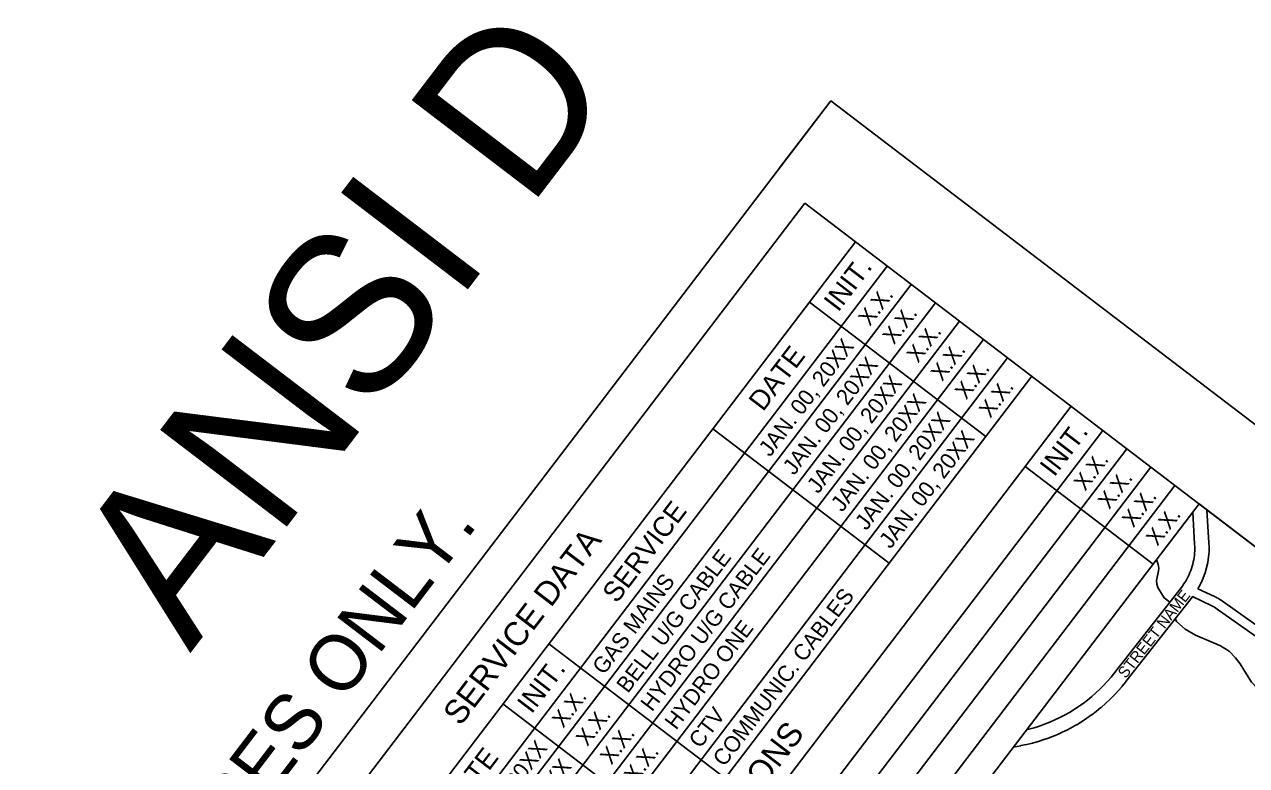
# Model space of a CAD drawing. Extents: x 599744 to 600217, y 4827560 to 4828065.
# Drawn here: x 599948.5 to 600025.2, y 4828018.5 to 4828065 of the extents above; entities that cross this region are included whole.
import ezdxf

# ---------------------------------------------------------------- set-up
doc = ezdxf.new("R2010")
doc.units = 0
for name, color, linetype in [('Default', 7, 'Continuous'), ('G-ANNO-KEYP', 7, 'Continuous'), ('G-ANNO-NPLT', 7, 'Continuous'), ('G-ANNO-TTLB-TEXT', 7, 'Continuous'), ('G-TTLB-OTLN', 7, 'Continuous'), ('G-TTLB-OTLN-PB', 7, 'Continuous')]:
    doc.layers.add(name, color=color, linetype=linetype)

msp = doc.modelspace()

# ---------------------------------------------------------------- linework, layer by layer
at = {"layer": 'G-ANNO-KEYP'}
for points in [[(600011.403, 4828020.775), (600011.528, 4828020.805), (600011.861, 4828020.898), (600012.189, 4828021.002), (600012.514, 4828021.117), (600012.835, 4828021.244), (600013.151, 4828021.381), (600013.462, 4828021.529), (600013.768, 4828021.688), (600014.069, 4828021.857), (600014.363, 4828022.037), (600014.651, 4828022.226), (600014.933, 4828022.425), (600015.207, 4828022.634), (600015.474, 4828022.851), (600015.734, 4828023.079), (600015.985, 4828023.314), (600016.229, 4828023.558), (600016.464, 4828023.811), (600016.69, 4828024.071), (600016.909, 4828024.342), (600021.07, 4828029.664), (600021.156, 4828029.778), (600021.236, 4828029.892), (600021.313, 4828030.009), (600021.385, 4828030.129), (600021.453, 4828030.251), (600021.516, 4828030.375), (600021.576, 4828030.501), (600021.631, 4828030.629), (600021.681, 4828030.76), (600021.727, 4828030.891), (600021.769, 4828031.024), (600021.806, 4828031.159), (600021.838, 4828031.295), (600021.865, 4828031.432), (600021.888, 4828031.57), (600021.906, 4828031.708), (600021.92, 4828031.847), (600021.928, 4828031.986), (600021.932, 4828032.126), (600021.93, 4828032.265), (600021.925, 4828032.382), (600021.925, 4828032.382), (600021.925, 4828032.382), (600021.924, 4828032.409), (600021.923, 4828032.435), (600021.804, 4828034.408)], [(600022.696, 4828034.553), (600022.821, 4828032.489), (600022.822, 4828032.459), (600022.822, 4828032.459), (600022.823, 4828032.452), (600022.824, 4828032.421), (600022.824, 4828032.421), (600022.829, 4828032.296), (600022.829, 4828032.295), (600022.83, 4828032.281), (600022.831, 4828032.126), (600022.83, 4828032.123), (600022.831, 4828032.11), (600022.827, 4828031.955), (600022.826, 4828031.952), (600022.826, 4828031.94), (600022.817, 4828031.785), (600022.815, 4828031.781), (600022.816, 4828031.769), (600022.801, 4828031.615), (600022.799, 4828031.611), (600022.799, 4828031.6), (600022.779, 4828031.446), (600022.777, 4828031.441), (600022.777, 4828031.43), (600022.752, 4828031.278), (600022.749, 4828031.272), (600022.749, 4828031.262), (600022.718, 4828031.11), (600022.715, 4828031.104), (600022.715, 4828031.095), (600022.679, 4828030.944), (600022.676, 4828030.937)], [(600020.365, 4828028.762), (600020.024, 4828029.037), (600019.608, 4828029.696), (600019.55, 4828029.892), (600019.527, 4828030.122), (600019.653, 4828030.741), (600019.675, 4828030.912), (600019.643, 4828031.141), (600019.541, 4828031.442)], [(600022.676, 4828030.937), (600022.675, 4828030.929), (600022.634, 4828030.78), (600022.631, 4828030.772), (600022.63, 4828030.765), (600022.584, 4828030.617), (600022.58, 4828030.609), (600022.579, 4828030.602), (600022.528, 4828030.456), (600022.523, 4828030.447), (600022.523, 4828030.441), (600022.466, 4828030.297), (600022.461, 4828030.287), (600022.46, 4828030.282), (600022.399, 4828030.14), (600022.394, 4828030.13), (600022.393, 4828030.126), (600022.327, 4828029.985), (600022.321, 4828029.975), (600022.32, 4828029.971), (600022.249, 4828029.833), (600022.243, 4828029.823), (600022.242, 4828029.82), (600022.167, 4828029.684), (600022.159, 4828029.673), (600022.159, 4828029.671), (600022.125, 4828029.615)], [(600021.796, 4828029.132), (600021.786, 4828029.119), (600021.781, 4828029.113), (600021.781, 4828029.113), (600017.615, 4828023.785), (600017.615, 4828023.785), (600017.61, 4828023.779), (600017.384, 4828023.499), (600017.383, 4828023.499), (600017.374, 4828023.487), (600017.138, 4828023.215), (600017.137, 4828023.215), (600017.127, 4828023.204), (600016.882, 4828022.94), (600016.88, 4828022.939), (600016.871, 4828022.929), (600016.617, 4828022.674), (600016.615, 4828022.673), (600016.606, 4828022.663), (600016.343, 4828022.417), (600016.34, 4828022.416), (600016.332, 4828022.407), (600016.061, 4828022.169), (600016.057, 4828022.168), (600016.049, 4828022.159), (600015.77, 4828021.932), (600015.765, 4828021.93), (600015.758, 4828021.922), (600015.471, 4828021.704), (600015.466, 4828021.702), (600015.458, 4828021.695), (600015.164, 4828021.487), (600015.159, 4828021.485), (600015.152, 4828021.478), (600014.851, 4828021.281), (600014.844, 4828021.278), (600014.838, 4828021.272), (600014.53, 4828021.085), (600014.523, 4828021.083), (600014.517, 4828021.077), (600014.203, 4828020.901), (600014.195, 4828020.898), (600014.189, 4828020.893), (600013.869, 4828020.727), (600013.861, 4828020.725), (600013.856, 4828020.721), (600013.53, 4828020.566), (600013.521, 4828020.563), (600013.516, 4828020.559), (600013.186, 4828020.416), (600013.176, 4828020.413), (600013.172, 4828020.41), (600012.837, 4828020.278), (600012.826, 4828020.275), (600012.822, 4828020.272), (600012.483, 4828020.152), (600012.471, 4828020.149), (600012.468, 4828020.147), (600012.125, 4828020.038), (600012.113, 4828020.035), (600012.11, 4828020.034), (600011.763, 4828019.937), (600011.75, 4828019.934), (600011.748, 4828019.933), (600011.398, 4828019.848), (600011.385, 4828019.845), (600011.383, 4828019.844)], [(600026.724, 4828025.939), (600023.332, 4828028.341), (600023.251, 4828028.396), (600023.169, 4828028.447), (600023.086, 4828028.496), (600023.001, 4828028.541), (600021.796, 4828029.132)], [(600027.068, 4828026.429), (600023.676, 4828028.831), (600023.675, 4828028.831), (600023.671, 4828028.834), (600023.583, 4828028.894), (600023.582, 4828028.894), (600023.574, 4828028.9), (600023.484, 4828028.957), (600023.483, 4828028.957), (600023.475, 4828028.962), (600023.383, 4828029.016), (600023.381, 4828029.016), (600023.373, 4828029.021), (600023.279, 4828029.072), (600023.277, 4828029.072), (600023.27, 4828029.076), (600023.174, 4828029.123), (600023.173, 4828029.124), (600023.169, 4828029.126), (600022.125, 4828029.615)], [(600031.423, 4828022.843), (600031.069, 4828022.999), (600030.258, 4828023.267), (600029.409, 4828023.358), (600028.876, 4828023.215), (600028.192, 4828022.961), (600027.646, 4828022.814), (600027.113, 4828022.802), (600026.619, 4828022.899), (600026.276, 4828023.086), (600025.874, 4828023.361), (600025.496, 4828023.753), (600025.019, 4828024.527), (600024.778, 4828024.893), (600024.478, 4828025.28), (600024.088, 4828025.705), (600023.545, 4828026.035), (600022.805, 4828026.349), (600021.978, 4828026.699), (600021.327, 4828027.074), (600020.789, 4828027.56), (600020.706, 4828027.738)], [(600011.383, 4828019.844), (600011.031, 4828019.771), (600011.023, 4828019.77), (600011.023, 4828019.77), (600010.572, 4828019.685)]]:
    msp.add_lwpolyline(points, dxfattribs=at)
at = {"layer": 'G-TTLB-OTLN'}
for p, q in [((599758.445, 4827740.467), (599997.478, 4828053.792)), ((599997.478, 4828053.792), (600211.005, 4827890.894)), ((600000.656, 4828051.367), (599962.201, 4828000.96)), ((599962.203, 4828000.958), (600000.658, 4828051.366)), ((600002.644, 4828049.851), (599964.188, 4827999.443)), ((600004.155, 4828048.698), (599965.699, 4827998.291)), ((600005.665, 4828047.546), (599967.21, 4827997.138)), ((599997.775, 4828047.591), (600008.826, 4828039.16)), ((600007.176, 4828046.394), (599968.72, 4827995.986)), ((600008.686, 4828045.241), (599970.231, 4827994.834)), ((600010.197, 4828044.089), (599971.741, 4827993.681)), ((600011.708, 4828042.936), (599973.252, 4827992.529)), ((600014.172, 4828041.056), (599975.717, 4827990.648)), ((600016.16, 4828039.54), (599977.704, 4827989.132)), ((599991.71, 4828039.64), (600002.761, 4828031.209)), ((600017.67, 4828038.387), (599979.215, 4827987.98)), ((600019.181, 4828037.235), (599980.725, 4827986.827)), ((600011.292, 4828037.28), (600019.322, 4828031.154)), ((600020.692, 4828036.082), (599982.236, 4827985.675)), ((599981.429, 4828026.164), (599992.48, 4828017.733)), ((599978.548, 4828022.387), (599989.599, 4828013.956))]:
    msp.add_line(p, q, dxfattribs=at)
msp.add_lwpolyline([(599983.747, 4827984.522), (600022.202, 4828034.93), (600058.02, 4828007.605), (600019.565, 4827957.197)], close=True, dxfattribs=at)
at = {"layer": 'G-TTLB-OTLN-PB'}
for p, q in [((599995.896, 4828056.005), (599999.105, 4828060.212)), ((599999.105, 4828060.212), (600003.873, 4828056.575))]:
    msp.add_line(p, q, dxfattribs=at)
msp.add_lwpolyline([(599961.599, 4827559.688), (600216.766, 4827894.161), (599999.104, 4828060.213), (599743.938, 4827725.74)], close=True, dxfattribs=at)

# ---------------------------------------------------------------- texts
at = {"layer": 'Default'}
msp.add_text('THIS DRAWING SAMPLE IS INTENDED TO ILLUSTRATE THE NEW CAD STANDARDS FOR ROAD WORKS AND SHOULD BE USED FOR REFERENCE PURPOSES ONLY.', height=3.5, rotation=52.66028, dxfattribs=at).set_placement((599752.419, 4827739.237))
at = {"layer": 'G-ANNO-KEYP'}
msp.add_text('STREET NAME', height=0.7, rotation=51.97933, dxfattribs=at).set_placement((600017.599, 4828023.943))
at = {"layer": 'G-ANNO-NPLT'}
msp.add_text('ANSI D', height=10, rotation=52.66028, dxfattribs=at).set_placement((599958.926, 4828025.549))
at = {"layer": 'G-ANNO-TTLB-TEXT'}
for s, height, rotation, p in [('INIT.', 1.25, 52.66028, (599999.57, 4828046.917)), ('X.X.', 1, 52.66023, (600001.555, 4828046.034)), ('X.X.', 1, 52.66023, (600003.066, 4828044.881)), ('X.X.', 1, 52.66023, (600004.577, 4828043.729)), ('JAN. 00, 20XX', 1, 52.66023, (599995.298, 4828037.83)), ('DATE', 1.25, 52.66028, (599994.86, 4828040.677)), ('X.X.', 1, 52.66023, (600006.088, 4828042.576)), ('JAN. 00, 20XX', 1, 52.66023, (599996.809, 4828036.677)), ('X.X.', 1, 52.66023, (600007.599, 4828041.423)), ('JAN. 00, 20XX', 1, 52.66023, (599998.32, 4828035.524)), ('X.X.', 1, 52.66023, (600009.109, 4828040.271)), ('JAN. 00, 20XX', 1, 52.66023, (599999.83, 4828034.372)), ('JAN. 00, 20XX', 1, 52.66023, (600001.342, 4828033.219)), ('INIT.', 1.25, 52.66028, (600013.118, 4828036.581)), ('JAN. 00, 20XX', 1, 52.66023, (600002.852, 4828032.067)), ('X.X.', 1, 52.66023, (600015.056, 4828035.7)), ('X.X.', 1, 52.66023, (600016.566, 4828034.547)), ('SERVICE', 1.25, 52.66028, (599985.684, 4828028.65)), ('X.X.', 1, 52.66023, (600018.078, 4828033.395)), ('X.X.', 1, 52.66023, (600019.587, 4828032.242)), ('SERVICE DATA', 1.5, 52.66028, (599975.877, 4828020.947)), ('BELL U/G CABLE', 1, 52.66028, (599986.382, 4828023.009)), ('HYDRO U/G CABLE', 1, 52.66028, (599987.893, 4828021.856)), ('GAS MAINS', 1, 52.66028, (599984.871, 4828024.162)), ('COMMUNIC. CABLES', 1, 52.66028, (599992.425, 4828018.399)), ('HYDRO ONE', 1, 52.66028, (599989.404, 4828020.704)), ('INIT.', 1.25, 52.66028, (599980.342, 4828021.714)), ('X.X.', 1, 52.66023, (599982.328, 4828020.831)), ('CTV', 1, 52.66028, (599990.915, 4828019.551)), ('X.X.', 1, 52.66023, (599983.839, 4828019.678)), ('X.X.', 1, 52.66023, (599985.35, 4828018.525)), ('REVISIONS', 1.5, 52.66028, (599990.881, 4828011.843)), ('JAN. 00, 20XX', 1, 52.66023, (599976.069, 4828012.627)), ('DATE', 1.25, 52.66028, (599975.631, 4828015.475)), ('JAN. 00, 20XX', 1, 52.66023, (599977.58, 4828011.475)), ('X.X.', 1, 52.66023, (599986.86, 4828017.373))]:
    msp.add_text(s, height=height, rotation=rotation, dxfattribs=at).set_placement(p)

doc.saveas('drawing.dxf')
